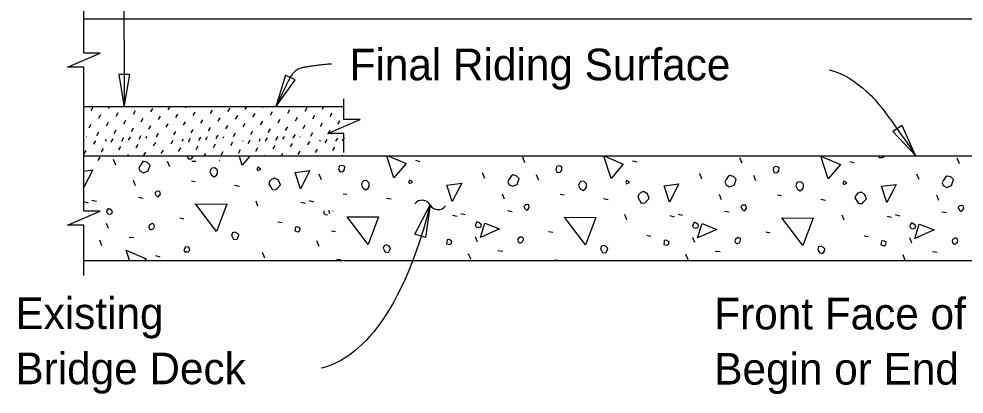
# Model space of a CAD drawing. Extents: x 21526.6 to 21595.9, y 56117 to 56157.3.
# Drawn here: x 21526.83 to 21532.85, y 56132.82 to 56135.21 of the extents above; entities that cross this region are included whole.
import ezdxf

# ---------------------------------------------------------------- set-up
doc = ezdxf.new("R2010")
doc.units = 0
for name, color, linetype in [('AdhocPoint_dp', 7, 'Continuous'), ('Border', 7, 'Continuous'), ('Patterning', 7, 'Continuous'), ('PlotBorder_dp', 7, 'Continuous')]:
    doc.layers.add(name, color=color, linetype=linetype)

msp = doc.modelspace()

# ---------------------------------------------------------------- linework, layer by layer
at = {"layer": 'AdhocPoint_dp'}
for p, q in [((21527.2426, 56135.21), (21535.6096, 56135.21)), ((21528.9006, 56134.6484), (21527.2426, 56134.6484)), ((21535.6096, 56134.335), (21527.2426, 56134.335)), ((21527.2426, 56133.6684), (21535.6096, 56133.6684))]:
    msp.add_line(p, q, dxfattribs=at)
at = {"layer": 'Patterning'}
for p, q in [((21527.2896, 56134.6259), (21527.3025, 56134.6483)), ((21527.3384, 56134.577), (21527.3514, 56134.5994)), ((21527.4002, 56134.6388), (21527.4057, 56134.6484)), ((21527.449, 56134.59), (21527.462, 56134.6124)), ((21527.5597, 56134.603), (21527.5726, 56134.6254)), ((21527.6703, 56134.6159), (21527.6833, 56134.6383)), ((21527.7809, 56134.6289), (21527.7922, 56134.6484)), ((21527.8298, 56134.5801), (21527.8427, 56134.6025)), ((21527.8916, 56134.6419), (21527.8953, 56134.6484)), ((21527.9404, 56134.593), (21527.9534, 56134.6154)), ((21528.051, 56134.606), (21528.064, 56134.6284)), ((21528.1617, 56134.619), (21528.1746, 56134.6413)), ((21528.2105, 56134.5701), (21528.2235, 56134.5925)), ((21528.2723, 56134.6319), (21528.2818, 56134.6484)), ((21528.3211, 56134.5831), (21528.3341, 56134.6055)), ((21528.3829, 56134.6449), (21528.3849, 56134.6484)), ((21528.4318, 56134.596), (21528.4447, 56134.6184)), ((21528.5424, 56134.609), (21528.5553, 56134.6314)), ((21528.653, 56134.622), (21528.666, 56134.6444)), ((21528.7019, 56134.5731), (21528.7148, 56134.5955)), ((21528.7637, 56134.6349), (21528.7714, 56134.6484)), ((21528.8125, 56134.5861), (21528.8254, 56134.6085)), ((21528.8743, 56134.6479), (21528.8745, 56134.6484)), ((21527.2766, 56134.5152), (21527.2896, 56134.5376)), ((21527.3872, 56134.5282), (21527.4002, 56134.5506)), ((21527.4979, 56134.5412), (21527.5108, 56134.5636)), ((21527.6085, 56134.5541), (21527.6215, 56134.5765)), ((21527.7191, 56134.5671), (21527.7321, 56134.5895)), ((21527.768, 56134.5183), (21527.7809, 56134.5407)), ((21527.8786, 56134.5312), (21527.8916, 56134.5536)), ((21527.9892, 56134.5442), (21528.0022, 56134.5666)), ((21528.0999, 56134.5572), (21528.1128, 56134.5795)), ((21528.2593, 56134.5213), (21528.2723, 56134.5437)), ((21528.37, 56134.5342), (21528.3829, 56134.5566)), ((21528.4806, 56134.5472), (21528.4936, 56134.5696)), ((21528.5912, 56134.5602), (21528.6042, 56134.5826)), ((21528.6401, 56134.5113), (21528.653, 56134.5337)), ((21528.7507, 56134.5243), (21528.7637, 56134.5467)), ((21528.8613, 56134.5373), (21528.8743, 56134.5597)), ((21527.3254, 56134.4664), (21527.3384, 56134.4888)), ((21527.4361, 56134.4794), (21527.449, 56134.5018)), ((21527.5467, 56134.4923), (21527.5597, 56134.5147)), ((21527.6573, 56134.5053), (21527.6703, 56134.5277)), ((21527.7062, 56134.4565), (21527.7191, 56134.4789)), ((21527.8168, 56134.4694), (21527.8298, 56134.4918)), ((21527.9274, 56134.4824), (21527.9404, 56134.5048)), ((21528.0381, 56134.4954), (21528.051, 56134.5177)), ((21528.1487, 56134.5083), (21528.1617, 56134.5307)), ((21528.1975, 56134.4595), (21528.2105, 56134.4819)), ((21528.3082, 56134.4724), (21528.3211, 56134.4948)), ((21528.4188, 56134.4854), (21528.4318, 56134.5078)), ((21528.5294, 56134.4984), (21528.5424, 56134.5208)), ((21528.5783, 56134.4495), (21528.5912, 56134.4719)), ((21528.6889, 56134.4625), (21528.7019, 56134.4849)), ((21528.7995, 56134.4755), (21528.8125, 56134.4979)), ((21528.9102, 56134.4884), (21528.9103, 56134.4886)), ((21527.2583, 56134.4585), (21527.2592, 56134.46)), ((21527.3071, 56134.4097), (21527.3201, 56134.4321)), ((21527.3811, 56134.4294), (21527.3872, 56134.44)), ((21527.4178, 56134.4226), (21527.4307, 56134.445)), ((21527.4849, 56134.4305), (21527.4979, 56134.4529)), ((21527.5284, 56134.4356), (21527.5413, 56134.458)), ((21527.5955, 56134.4435), (21527.6085, 56134.4659)), ((21527.639, 56134.4486), (21527.6457, 56134.46)), ((21527.6879, 56134.3997), (21527.7008, 56134.4221)), ((21527.7676, 56134.4294), (21527.768, 56134.43)), ((21527.7985, 56134.4127), (21527.8114, 56134.4351)), ((21527.8707, 56134.4294), (21527.8786, 56134.443)), ((21527.9091, 56134.4257), (21527.9221, 56134.4481)), ((21527.9763, 56134.4336), (21527.9892, 56134.4559)), ((21528.0198, 56134.4386), (21528.0321, 56134.46)), ((21528.0686, 56134.3898), (21528.0815, 56134.4122)), ((21528.0869, 56134.4465), (21528.0999, 56134.4689)), ((21528.1304, 56134.4516), (21528.1353, 56134.46)), ((21528.1792, 56134.4028), (21528.1922, 56134.4251)), ((21528.2572, 56134.4294), (21528.2593, 56134.433)), ((21528.2899, 56134.4157), (21528.3028, 56134.4381)), ((21528.3603, 56134.4294), (21528.37, 56134.446)), ((21528.4005, 56134.4287), (21528.4134, 56134.4511)), ((21528.4676, 56134.4366), (21528.4806, 56134.459)), ((21528.5111, 56134.4416), (21528.5218, 56134.46)), ((21528.56, 56134.3928), (21528.5729, 56134.4152)), ((21528.6217, 56134.4546), (21528.6249, 56134.46)), ((21528.6706, 56134.4058), (21528.6835, 56134.4282)), ((21528.7468, 56134.4294), (21528.7507, 56134.4361)), ((21528.7812, 56134.4187), (21528.7942, 56134.4411)), ((21528.8499, 56134.4294), (21528.8613, 56134.449)), ((21528.8918, 56134.4317), (21528.9048, 56134.4541)), ((21527.2453, 56134.3479), (21527.2583, 56134.3703)), ((21527.356, 56134.3608), (21527.3689, 56134.3832)), ((21527.4666, 56134.3738), (21527.4796, 56134.3962)), ((21527.5772, 56134.3868), (21527.5902, 56134.4092)), ((21527.6261, 56134.3379), (21527.639, 56134.3603)), ((21527.7367, 56134.3509), (21527.7497, 56134.3733)), ((21527.8473, 56134.3639), (21527.8603, 56134.3863)), ((21527.958, 56134.3768), (21527.9709, 56134.3992)), ((21528.1174, 56134.341), (21528.1304, 56134.3633)), ((21528.2281, 56134.3539), (21528.241, 56134.3763)), ((21528.3387, 56134.3669), (21528.3516, 56134.3893)), ((21528.4493, 56134.3798), (21528.4623, 56134.4022)), ((21528.5005, 56134.335), (21528.5111, 56134.3534)), ((21528.6088, 56134.344), (21528.6217, 56134.3664)), ((21528.7194, 56134.3569), (21528.7324, 56134.3793)), ((21528.8301, 56134.3699), (21528.843, 56134.3923)), ((21527.3349, 56134.3055), (21527.3478, 56134.3279)), ((21527.4465, 56134.2767), (21527.4324, 56134.3121)), ((21527.5212, 56134.335), (21527.5284, 56134.3474)), ((21527.6176, 56134.3044), (21527.6179, 56134.305)), ((21527.7906, 56134.265), (21527.7765, 56134.3003)), ((21527.9077, 56134.335), (21527.9091, 56134.3374)), ((21528.0109, 56134.335), (21528.0198, 56134.3504)), ((21528.1072, 56134.3044), (21528.1093, 56134.308)), ((21528.3974, 56134.335), (21528.4005, 56134.3404)), ((21528.887, 56134.335), (21528.8918, 56134.3435)), ((21529.3562, 56134.3079), (21529.3845, 56134.3008)), ((21530.0545, 56134.292), (21530.0403, 56134.3273)), ((21530.7409, 56134.3043), (21530.7691, 56134.2973)), ((21531.4391, 56134.2884), (21531.425, 56134.3238)), ((21532.1255, 56134.3008), (21532.1538, 56134.2937)), ((21532.8238, 56134.2849), (21532.8097, 56134.3203)), ((21527.572, 56134.1442), (21527.5597, 56134.1777)), ((21527.9285, 56134.1766), (21527.9533, 56134.1731)), ((21528.7575, 56134.183), (21528.7434, 56134.2183)), ((21529.7981, 56134.1912), (21529.784, 56134.2266)), ((21530.1422, 56134.1795), (21530.1281, 56134.2148)), ((21531.1828, 56134.1877), (21531.1687, 56134.223)), ((21531.5269, 56134.1759), (21531.5128, 56134.2113)), ((21532.5675, 56134.1841), (21532.5533, 56134.2195)), ((21528.2043, 56134.1483), (21528.2343, 56134.143)), ((21527.2945, 56134.054), (21527.3228, 56134.0469)), ((21527.5909, 56134.0723), (21527.6209, 56134.067)), ((21528.6792, 56134.0505), (21528.7075, 56134.0434)), ((21528.8954, 56134.0946), (21528.9202, 56134.0911)), ((21529.1712, 56134.0663), (21529.2012, 56134.061)), ((21529.9236, 56134.0586), (21529.9113, 56134.0922)), ((21530.2801, 56134.0911), (21530.3049, 56134.0875)), ((21530.5559, 56134.0628), (21530.5859, 56134.0575)), ((21531.3083, 56134.0551), (21531.2959, 56134.0887)), ((21531.6648, 56134.0875), (21531.6895, 56134.084)), ((21531.9406, 56134.0593), (21531.9706, 56134.0539)), ((21532.693, 56134.0516), (21532.6806, 56134.0851)), ((21527.2421, 56134.044), (21527.2704, 56134.037)), ((21528.3528, 56134.014), (21528.3404, 56134.0476)), ((21528.6268, 56134.0405), (21528.6551, 56134.0334)), ((21527.8543, 56133.9397), (21527.8808, 56133.9344)), ((21529.5937, 56133.9585), (21529.622, 56133.9514)), ((21529.6461, 56133.9685), (21529.6744, 56133.9614)), ((21529.9425, 56133.9868), (21529.9725, 56133.9815)), ((21530.7044, 56133.9284), (21530.692, 56133.962)), ((21530.9784, 56133.955), (21531.0067, 56133.9479)), ((21531.0308, 56133.9649), (21531.0591, 56133.9579)), ((21531.3271, 56133.9832), (21531.3572, 56133.9779)), ((21532.089, 56133.9249), (21532.0767, 56133.9585)), ((21532.363, 56133.9514), (21532.3913, 56133.9443)), ((21532.4155, 56133.9614), (21532.4437, 56133.9543)), ((21532.7118, 56133.9797), (21532.7419, 56133.9744)), ((21527.4006, 56133.8714), (21527.3882, 56133.905)), ((21528.48, 56133.915), (21528.5066, 56133.9097)), ((21527.5308, 56133.8177), (21527.5626, 56133.8142)), ((21528.8212, 56133.8577), (21528.8477, 56133.8524)), ((21529.7522, 56133.7859), (21529.7398, 56133.8195)), ((21530.2059, 56133.8542), (21530.2324, 56133.8489)), ((21530.8316, 56133.8294), (21530.8582, 56133.8241)), ((21531.1368, 56133.7823), (21531.1245, 56133.8159)), ((21531.5905, 56133.8507), (21531.6171, 56133.8454)), ((21532.2163, 56133.8259), (21532.2428, 56133.8206)), ((21532.5215, 56133.7788), (21532.5091, 56133.8124)), ((21527.3581, 56133.7618), (21527.344, 56133.7972)), ((21528.7428, 56133.7583), (21528.7287, 56133.7936)), ((21527.6987, 56133.6993), (21527.727, 56133.6922)), ((21528.397, 56133.6834), (21528.3828, 56133.7188)), ((21529.7097, 56133.6763), (21529.6956, 56133.7116)), ((21529.8824, 56133.7322), (21529.9142, 56133.7287)), ((21531.0944, 56133.6727), (21531.0803, 56133.7081)), ((21531.267, 56133.7287), (21531.2989, 56133.7251)), ((21532.4791, 56133.6692), (21532.465, 56133.7046)), ((21532.6517, 56133.7251), (21532.6835, 56133.7216))]:
    msp.add_line(p, q, dxfattribs=at)
for points in [[(21527.6003, 56134.2396), (21527.6233, 56134.2272), (21527.6534, 56134.2396), (21527.6657, 56134.2767), (21527.6481, 56134.2944), (21527.6251, 56134.2997), (21527.6145, 56134.2927), (21527.6021, 56134.2732), (21527.5933, 56134.2573), (21527.6003, 56134.2396)], [(21527.9005, 56134.3317), (21527.9091, 56134.3163), (21527.9285, 56134.318), (21527.9373, 56134.3304), (21527.9375, 56134.3317)], [(21527.9326, 56134.3044), (21527.9336, 56134.302), (21527.9312, 56134.3044)], [(21527.9336, 56134.302), (21527.9548, 56134.302), (21527.9572, 56134.3044)], [(21528.252, 56134.2774), (21528.2343, 56134.3317)], [(21528.298, 56134.3317), (21528.252, 56134.2774)], [(21529.2189, 56134.1954), (21529.1735, 56134.335)], [(21529.1874, 56134.335), (21529.2967, 56134.2873), (21529.2189, 56134.1954)], [(21530.6036, 56134.1918), (21530.557, 56134.335)], [(21530.564, 56134.335), (21530.6814, 56134.2838), (21530.6036, 56134.1918)], [(21531.9883, 56134.1883), (21531.9406, 56134.335), (21532.0661, 56134.2802), (21531.9883, 56134.1883)], [(21532.3089, 56134.335), (21532.3129, 56134.3256), (21532.3094, 56134.3291)], [(21532.3129, 56134.3256), (21532.3341, 56134.3256), (21532.3436, 56134.335)], [(21527.2426, 56134.2391), (21527.2998, 56134.2467), (21527.2427, 56134.1358)], [(21528.0452, 56134.2332), (21528.0558, 56134.212), (21528.0735, 56134.2014), (21528.0876, 56134.212), (21528.0947, 56134.2226), (21528.0947, 56134.2438), (21528.0788, 56134.2597), (21528.0593, 56134.2579), (21528.0505, 56134.2491), (21528.0452, 56134.2332)], [(21528.351, 56134.242), (21528.3704, 56134.2509), (21528.3634, 56134.2579), (21528.351, 56134.2632), (21528.3457, 56134.2509), (21528.351, 56134.242)], [(21528.6244, 56134.1265), (21528.5908, 56134.2308), (21528.6845, 56134.2432), (21528.6244, 56134.1265)], [(21528.8671, 56134.2502), (21528.876, 56134.2343), (21528.8954, 56134.236), (21528.9043, 56134.2484), (21528.906, 56134.2678), (21528.8937, 56134.2731), (21528.8848, 56134.2749), (21528.8742, 56134.2714), (21528.8707, 56134.2678), (21528.8671, 56134.2502)], [(21530.2518, 56134.2466), (21530.2607, 56134.2307), (21530.2801, 56134.2325), (21530.2889, 56134.2449), (21530.2907, 56134.2643), (21530.2783, 56134.2696), (21530.2695, 56134.2714), (21530.2589, 56134.2678), (21530.2554, 56134.2643), (21530.2518, 56134.2466)], [(21531.6365, 56134.2431), (21531.6453, 56134.2272), (21531.6648, 56134.229), (21531.6736, 56134.2413), (21531.6754, 56134.2608), (21531.663, 56134.2661), (21531.6542, 56134.2678), (21531.6436, 56134.2643), (21531.64, 56134.2608), (21531.6365, 56134.2431)], [(21528.4217, 56134.1572), (21528.4447, 56134.12), (21528.4677, 56134.1218), (21528.4765, 56134.1306), (21528.496, 56134.1501), (21528.4836, 56134.1801), (21528.4588, 56134.1943), (21528.4412, 56134.1872), (21528.427, 56134.1731), (21528.4217, 56134.1572)], [(21529.0121, 56134.1512), (21529.0227, 56134.13), (21529.0404, 56134.1194), (21529.0545, 56134.13), (21529.0616, 56134.1406), (21529.0616, 56134.1618), (21529.0457, 56134.1777), (21529.0262, 56134.1759), (21529.0174, 56134.1671), (21529.0121, 56134.1512)], [(21529.3179, 56134.16), (21529.3374, 56134.1689), (21529.3303, 56134.1759), (21529.3179, 56134.1812), (21529.3126, 56134.1689), (21529.3179, 56134.16)], [(21529.9519, 56134.1541), (21529.9749, 56134.1417), (21530.005, 56134.1541), (21530.0173, 56134.1912), (21529.9997, 56134.2089), (21529.9767, 56134.2142), (21529.9661, 56134.2071), (21529.9537, 56134.1877), (21529.9449, 56134.1718), (21529.9519, 56134.1541)], [(21530.3968, 56134.1476), (21530.4074, 56134.1264), (21530.4251, 56134.1158), (21530.4392, 56134.1264), (21530.4463, 56134.137), (21530.4463, 56134.1582), (21530.4304, 56134.1742), (21530.4109, 56134.1724), (21530.4021, 56134.1635), (21530.3968, 56134.1476)], [(21530.7026, 56134.1565), (21530.722, 56134.1653), (21530.715, 56134.1724), (21530.7026, 56134.1777), (21530.6973, 56134.1653), (21530.7026, 56134.1565)], [(21531.3366, 56134.1505), (21531.3596, 56134.1382), (21531.3896, 56134.1505), (21531.402, 56134.1877), (21531.3843, 56134.2053), (21531.3614, 56134.2107), (21531.3507, 56134.2036), (21531.3384, 56134.1841), (21531.3295, 56134.1682), (21531.3366, 56134.1505)], [(21531.7815, 56134.1441), (21531.7921, 56134.1229), (21531.8097, 56134.1123), (21531.8239, 56134.1229), (21531.831, 56134.1335), (21531.831, 56134.1547), (21531.815, 56134.1706), (21531.7956, 56134.1689), (21531.7868, 56134.16), (21531.7815, 56134.1441)], [(21532.0873, 56134.1529), (21532.1067, 56134.1618), (21532.0997, 56134.1689), (21532.0873, 56134.1742), (21532.082, 56134.1618), (21532.0873, 56134.1529)], [(21532.7213, 56134.147), (21532.7443, 56134.1346), (21532.7743, 56134.147), (21532.7867, 56134.1841), (21532.769, 56134.2018), (21532.746, 56134.2071), (21532.7354, 56134.2), (21532.723, 56134.1806), (21532.7142, 56134.1647), (21532.7213, 56134.147)], [(21527.7022, 56134.0847), (21527.7128, 56134.0741), (21527.7234, 56134.0811), (21527.7305, 56134.0918), (21527.727, 56134.1094), (21527.7181, 56134.1112), (21527.7058, 56134.1094), (21527.6952, 56134.0988), (21527.7022, 56134.0847)], [(21529.5913, 56134.0445), (21529.5577, 56134.1488), (21529.6514, 56134.1612), (21529.5913, 56134.0445)], [(21530.976, 56134.0409), (21530.9424, 56134.1452), (21531.0361, 56134.1576), (21530.976, 56134.0409)], [(21532.3607, 56134.0374), (21532.3271, 56134.1417), (21532.4208, 56134.1541), (21532.3607, 56134.0374)], [(21530.7733, 56134.0716), (21530.7963, 56134.0345), (21530.8193, 56134.0363), (21530.8281, 56134.0451), (21530.8476, 56134.0646), (21530.8352, 56134.0946), (21530.8104, 56134.1087), (21530.7928, 56134.1017), (21530.7786, 56134.0875), (21530.7733, 56134.0716)], [(21532.158, 56134.0681), (21532.181, 56134.031), (21532.2039, 56134.0327), (21532.2128, 56134.0416), (21532.2322, 56134.061), (21532.2199, 56134.0911), (21532.1951, 56134.1052), (21532.1774, 56134.0981), (21532.1633, 56134.084), (21532.158, 56134.0681)], [(21527.397, 56133.9656), (21527.4094, 56133.9638), (21527.4218, 56133.9692), (21527.4253, 56133.9798), (21527.42, 56133.9886), (21527.4094, 56133.9957), (21527.397, 56134.001), (21527.39, 56133.9868), (21527.3864, 56133.9762), (21527.397, 56133.9656)], [(21528.0894, 56133.8531), (21527.955, 56134.0299), (21528.1548, 56134.0281), (21528.0894, 56133.8531)], [(21530.0538, 56133.9991), (21530.0644, 56133.9885), (21530.075, 56133.9956), (21530.0821, 56134.0062), (21530.0786, 56134.0239), (21530.0697, 56134.0257), (21530.0574, 56134.0239), (21530.0468, 56134.0133), (21530.0538, 56133.9991)], [(21531.4385, 56133.9956), (21531.4491, 56133.985), (21531.4597, 56133.9921), (21531.4668, 56134.0027), (21531.4633, 56134.0204), (21531.4544, 56134.0221), (21531.442, 56134.0204), (21531.4314, 56134.0098), (21531.4385, 56133.9956)], [(21532.8232, 56133.9921), (21532.8338, 56133.9815), (21532.8444, 56133.9885), (21532.8515, 56133.9991), (21532.8479, 56134.0168), (21532.8391, 56134.0186), (21532.8267, 56134.0168), (21532.8161, 56134.0062), (21532.8232, 56133.9921)], [(21528.776, 56133.9861), (21528.7746, 56133.9833), (21528.7711, 56133.9727), (21528.7817, 56133.9621)], [(21528.7817, 56133.9621), (21528.7941, 56133.9603), (21528.796, 56133.9611)], [(21528.8073, 56133.9681), (21528.81, 56133.9762), (21528.8047, 56133.9851), (21528.8031, 56133.9861)], [(21528.8302, 56133.9823), (21528.8314, 56133.9861)], [(21529.0563, 56133.7711), (21528.9219, 56133.9479), (21529.1217, 56133.9461), (21529.0563, 56133.7711)], [(21530.441, 56133.7676), (21530.3066, 56133.9443), (21530.5064, 56133.9426), (21530.441, 56133.7676)], [(21531.8256, 56133.764), (21531.6913, 56133.9408), (21531.8911, 56133.939), (21531.8256, 56133.764)], [(21527.6669, 56133.8655), (21527.6739, 56133.8655), (21527.6881, 56133.8725), (21527.6934, 56133.8885), (21527.6916, 56133.8973), (21527.6775, 56133.9044), (21527.6598, 56133.8938), (21527.6563, 56133.8832), (21527.6598, 56133.8725), (21527.6669, 56133.8655)], [(21528.5879, 56133.8566), (21528.6073, 56133.8513), (21528.6197, 56133.8602), (21528.6215, 56133.8725), (21528.6179, 56133.8761), (21528.6038, 56133.8832), (21528.5914, 56133.8814), (21528.5897, 56133.869), (21528.5879, 56133.8566)], [(21529.7486, 56133.8801), (21529.761, 56133.8783), (21529.7734, 56133.8836), (21529.7769, 56133.8942), (21529.7716, 56133.9031), (21529.761, 56133.9101), (21529.7486, 56133.9154), (21529.7416, 56133.9013), (21529.738, 56133.8907), (21529.7486, 56133.8801)], [(21529.771, 56133.8153), (21529.7993, 56133.9072), (21529.893, 56133.8701), (21529.771, 56133.8153)], [(21531.1333, 56133.8765), (21531.1457, 56133.8748), (21531.1581, 56133.8801), (21531.1616, 56133.8907), (21531.1563, 56133.8995), (21531.1457, 56133.9066), (21531.1333, 56133.9119), (21531.1262, 56133.8978), (21531.1227, 56133.8872), (21531.1333, 56133.8765)], [(21531.1557, 56133.8118), (21531.1839, 56133.9037), (21531.2776, 56133.8666), (21531.1557, 56133.8118)], [(21532.518, 56133.873), (21532.5304, 56133.8712), (21532.5427, 56133.8765), (21532.5463, 56133.8872), (21532.541, 56133.896), (21532.5304, 56133.9031), (21532.518, 56133.9084), (21532.5109, 56133.8942), (21532.5074, 56133.8836), (21532.518, 56133.873)], [(21532.5403, 56133.8082), (21532.5686, 56133.9002), (21532.6623, 56133.863), (21532.5403, 56133.8082)], [(21528.1884, 56133.8213), (21528.1972, 56133.8054), (21528.2184, 56133.8018), (21528.2273, 56133.8177), (21528.2308, 56133.8319), (21528.222, 56133.8407), (21528.206, 56133.8496), (21528.1901, 56133.8443), (21528.1848, 56133.8284), (21528.1884, 56133.8213)], [(21530.0185, 56133.7799), (21530.0255, 56133.7799), (21530.0397, 56133.787), (21530.045, 56133.8029), (21530.0432, 56133.8118), (21530.0291, 56133.8188), (21530.0114, 56133.8082), (21530.0079, 56133.7976), (21530.0114, 56133.787), (21530.0185, 56133.7799)], [(21531.4032, 56133.7764), (21531.4102, 56133.7764), (21531.4244, 56133.7835), (21531.4297, 56133.7994), (21531.4279, 56133.8082), (21531.4138, 56133.8153), (21531.3961, 56133.8047), (21531.3925, 56133.7941), (21531.3961, 56133.7835), (21531.4032, 56133.7764)], [(21532.7878, 56133.7729), (21532.7949, 56133.7729), (21532.809, 56133.7799), (21532.8143, 56133.7959), (21532.8126, 56133.8047), (21532.7984, 56133.8118), (21532.7808, 56133.8012), (21532.7772, 56133.7905), (21532.7808, 56133.7799), (21532.7878, 56133.7729)], [(21527.8861, 56133.7241), (21527.9073, 56133.7241), (21527.9179, 56133.7347), (21527.9126, 56133.7541), (21527.8896, 56133.7559), (21527.8861, 56133.7453), (21527.8808, 56133.7364), (21527.8861, 56133.7241), (21527.8825, 56133.7276)], [(21529.1553, 56133.7393), (21529.1641, 56133.7234), (21529.1853, 56133.7198), (21529.1942, 56133.7357), (21529.1977, 56133.7499), (21529.1889, 56133.7587), (21529.173, 56133.7676), (21529.1571, 56133.7623), (21529.1518, 56133.7464), (21529.1553, 56133.7393)], [(21529.5548, 56133.7746), (21529.5742, 56133.7693), (21529.5866, 56133.7782), (21529.5884, 56133.7905), (21529.5849, 56133.7941), (21529.5707, 56133.8012), (21529.5583, 56133.7994), (21529.5566, 56133.787), (21529.5548, 56133.7746)], [(21530.54, 56133.7357), (21530.5488, 56133.7198), (21530.57, 56133.7163), (21530.5789, 56133.7322), (21530.5824, 56133.7464), (21530.5736, 56133.7552), (21530.5576, 56133.764), (21530.5417, 56133.7587), (21530.5364, 56133.7428), (21530.54, 56133.7357)], [(21530.9395, 56133.7711), (21530.9589, 56133.7658), (21530.9713, 56133.7746), (21530.9731, 56133.787), (21530.9695, 56133.7905), (21530.9554, 56133.7976), (21530.943, 56133.7959), (21530.9412, 56133.7835), (21530.9395, 56133.7711)], [(21531.9246, 56133.7322), (21531.9335, 56133.7163), (21531.9547, 56133.7128), (21531.9635, 56133.7287), (21531.9671, 56133.7428), (21531.9582, 56133.7517), (21531.9423, 56133.7605), (21531.9264, 56133.7552), (21531.9211, 56133.7393), (21531.9246, 56133.7322)], [(21532.3242, 56133.7676), (21532.3436, 56133.7623), (21532.356, 56133.7711), (21532.3577, 56133.7835), (21532.3542, 56133.787), (21532.3401, 56133.7941), (21532.3277, 56133.7923), (21532.3259, 56133.7799), (21532.3242, 56133.7676)], [(21527.536, 56133.665), (21527.5137, 56133.7335), (21527.6392, 56133.6787), (21527.6276, 56133.665)], [(21528.8805, 56133.6684), (21528.8795, 56133.6721), (21528.8565, 56133.6739), (21528.8547, 56133.6684)], [(21530.2643, 56133.6684), (21530.2642, 56133.6686), (21530.2412, 56133.6703), (21530.2406, 56133.6684)]]:
    msp.add_lwpolyline(points, dxfattribs=at)
at = {"layer": 'PlotBorder_dp'}
for points in [[(21527.2427, 56134.3351), (21527.2427, 56134.9021), (21527.1393, 56134.9021), (21527.2427, 56134.9471), (21527.346, 56134.9921), (21527.2427, 56134.9921), (21527.2427, 56135.3182)], [(21528.9006, 56134.3576), (21528.9006, 56134.4784), (21528.7973, 56134.4784), (21528.9006, 56134.5234), (21529.004, 56134.5684), (21528.9006, 56134.5684), (21528.9006, 56134.699)], [(21527.2427, 56133.5727), (21527.2427, 56133.8927), (21527.1393, 56133.8927), (21527.2427, 56133.9377), (21527.346, 56133.9827), (21527.2427, 56133.9827), (21527.2427, 56134.3351)]]:
    msp.add_lwpolyline(points, dxfattribs=at)
for points in [[(21527.5005, 56134.6471), (21527.5357, 56134.8553), (21527.4652, 56134.8553)], [(21528.466, 56134.6497), (21528.5907, 56134.8202), (21528.5275, 56134.8517)], [(21532.5451, 56134.338), (21532.4586, 56134.5307), (21532.3999, 56134.4914)], [(21529.4513, 56134.0231), (21529.4208, 56133.8141), (21529.3537, 56133.8358)]]:
    msp.add_lwpolyline(points, close=True, dxfattribs=at)
for centre, start, end in [((21529.3989, 56133.9934), 30.00813, 141.73535), ((21529.5022, 56134.053), 210.00813, 321.73535)]:
    msp.add_arc(centre, 0.0596, start, end, dxfattribs=at)
for points, degree in [([(21527.5433, 56139.7972), (21527.186, 56139.7968), (21527.352, 56139.3409), (21527.253, 56138.6974), (21527.5005, 56137.7639), (21527.5005, 56134.6471)], 2), ([(21528.8223, 56134.922), (21528.6486, 56134.9066), (21528.5744, 56134.8752), (21528.5088, 56134.7353), (21528.466, 56134.6497)], 2), ([(21531.9945, 56134.8857), (21532.0908, 56134.8619), (21532.246, 56134.7449), (21532.335, 56134.647), (21532.545, 56134.3379)], 3), ([(21529.4505, 56134.0233), (21529.2298, 56133.1495), (21528.8778, 56133.0078), (21528.7559, 56132.9813)], 3)]:
    msp.add_open_spline(points, degree=degree, dxfattribs=at)

# ---------------------------------------------------------------- texts
at = {"layer": 'Border'}
msp.add_text('Final Riding Surface', height=0.2016, dxfattribs=at).set_placement((21528.9369, 56134.8183))
at = {"layer": 'PlotBorder_dp'}
for s, p in [('Existing ', (21526.8068, 56133.2307)), ('Front Face of Backwall &', (21531.262, 56133.2284)), ('Bridge Deck', (21526.8068, 56132.8787)), ('Begin or End Bridge', (21531.262, 56132.8764))]:
    msp.add_text(s, height=0.2016, dxfattribs=at).set_placement(p)

doc.saveas('drawing.dxf')
